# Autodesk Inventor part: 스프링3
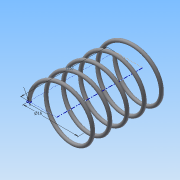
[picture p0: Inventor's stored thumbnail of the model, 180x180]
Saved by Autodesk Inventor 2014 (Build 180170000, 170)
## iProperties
Created: 2015-06
Part Number: 스프링3
Material: 강철, 연강
Document SubType Name: Modeling
Designer: Administrator
Density: 7.86 g/cm^3
Appearance: 강철
Mass: 1.52996 g
Surface Area: 7.87153 cm^2
Volume: 0.194652 cm^3
Author: Administrator
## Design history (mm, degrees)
sketch "스케치1"
  geometry: L1 (0, 0)-(-8, 0); L2 (-8, 0)-(-8, 14.5); L3 (-8, 14.5)-(0, 14.5); L4 (0, 14.5)-(0, 0); C1 r 0.5 at (-8, 0)
  constraints: 8 end point, 2 parallel, 1 centre point, 1 coincident, 1 horizontal, 1 perpendicular
  dimensions: "d0" = 1 diameter of C1; "d1" = 16 diameter of L2 L4; "d2" = 14.5 distance of L1.end L2.end (derived)
feature "코일1" sketch "스케치1" pitch "d3" = 10; turns "d5" = 5; dims "d4" = 14.5 (= d2), "d6" = 0, angle "d7" = 90 deg, angle "d8" = 90 deg, "d9" = 0, "d10" = 0
sketch "스케치2"
  geometry: L1 (8.5, 0)-(7.5, 0) reference; 1 further point
  constraints: 1 horizontal alignment
extrude "돌출1" cut sketch "스케치2" stored distance "d11" = 10; taper "d12" = 0 deg
node "작업 평면1"
sketch "스케치3"
  geometry: L1 (7.5, 0)-(8.5, 0) reference; 1 further point
  constraints: 1 horizontal alignment
extrude "돌출2" cut sketch "스케치3" stored distance "d14" = 10; taper "d15" = 0 deg
node "솔리드1"
node "절단 모서리 투영1"
node "절단 모서리 투영2"
other parameters: "d13" = 14.5 (= d2)
